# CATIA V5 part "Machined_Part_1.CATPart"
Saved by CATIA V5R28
Part number: Machined_Part
Bounding box of the stored display mesh (mm): x 0 to 279.4, y 0 to 152.586, z 0 to 50.8
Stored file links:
  C:\Users\rsz0866\Documents\007_CATIA_STEP-Files_and_Test_Models\0001_Machined_Parts_Models\Machined_Part_1.CATPart
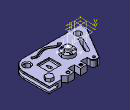
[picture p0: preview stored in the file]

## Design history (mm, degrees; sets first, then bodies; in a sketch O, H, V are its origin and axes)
AxisSystem1: origin (127, 76.2, 50.8), X (1, 0, 0), Y (0, 1, 0), Z (0, 0, 1)
Set1
  Sketch1 on xy-plane, origin (0, 0, 0), H (1, 0, 0), V (0, 1, 0)
    line L1 (0, 0) -> (279.4, 0)
    line L2 (279.4, 0) -> (279.4, 152.5862)
    line L3 (279.4, 152.5862) -> (228.6, 152.5862)
    line L4 (228.6, 152.5862) -> (216.7855, 136.1858)
    line L5 (216.7855, 136.1858) -> (202.7136, 152.5862)
    point P5 (202.7136, 152.5862)
    line L6 (177.3136, 152.5862) -> (177.3136, 127.1862)
    point P6 (177.3136, 152.5862)
    line L7 (202.7136, 152.5862) -> (177.3136, 152.5862)
    line L8 (177.3136, 127.1862) -> (151.9136, 127.1862)
    line L9 (151.9136, 127.1862) -> (151.9136, 152.5862)
    point P9 (151.9136, 152.5862)
    line L10 (151.9136, 152.5862) -> (126.5136, 152.5862)
    line L11 (126.5136, 152.5862) -> (126.5136, 127.1862)
    point P11 (126.5136, 127.1862)
    line L12 (101.1136, 127.1862) -> (101.1136, 152.5862)
    point P12 (101.1136, 127.1862)
    point P13 (101.1136, 152.5862)
    line L13 (101.1136, 152.5862) -> (75.7136, 152.5862)
    line L14 (75.7136, 152.5862) -> (0, 25.4)
    point P15 (0, 25.4)
    line L15 (0, 25.4) -> (0, 0)
    line L16 (101.1136, 127.1862) -> (126.5136, 127.1862)
    length L1 = 279.4
    length L3 = 50.8
    length L7 = 25.4
    length L8 = 25.4
    length L16 = 25.4
    length L10 = 25.4
    length L13 = 25.4
    length L15 = 25.4
    length L6 = 25.4
    horizontal: L1 H, L3 H, L7 H, L8 H, L10 H, L13 H, L16 H
    vertical: L2 V, L6 V, L9 V, L11 V, L12 V, L15 V
    coincidence: P5 L3, P6 L3, P9 L3, P11 L8, P12 L8, P13 L3, P15 V
Body1 (main body)
  Pad1: profile Sketch1, direction (0, 0, 1), length 25.4
  Fillet1: radius 50.8, on edge [face of Pad1 from Sketch1.L2 | face of Pad1 from Sketch1.L1]
  Sketch2 on face of Pad1 from Sketch1.L3, origin (0, 152.5862, 0), H (-1, 0, 0), V (0, 0, 1)
    line L1 (-281.8143, 19.05) -> (-243.7143, 19.05)
    line L2 (-243.7143, 19.05) -> (-243.7143, 6.35)
    line L3 (-243.7143, 6.35) -> (-281.8143, 6.35)
    line L4 (-281.8143, 6.35) -> (-281.8143, 19.05)
    reference projected line E1 (-279.4, 25.4) -> (-228.6, 25.4) from edge [face of Pad1 from Sketch1.L3 | end face of Pad1]
    reference projected line E2 (-279.4, 0) -> (-228.6, 0) from edge [start face of Pad1 | face of Pad1 from Sketch1.L3]
    distance L1 E1 = 6.35
    distance L3 E2 = 6.35
    length L1 = 38.1
    horizontal: L1 H, L3 H
    vertical: L2 V, L4 V
  Pocket1: profile Sketch2, direction (0, -1, 0), length 152.4
  Sketch3 on end face of Pad1, origin (0, 0, 25.4), H (1, 0, 0), V (0, 1, 0)
    circle A1 centre (247.65, 31.75) radius 12.7
    point P1 (247.65, 31.75)
    reference projected line E1 (0, 0) -> (279.4, 0) from edge [face of Pad1 from Sketch1.L1 | end face of Pad1]
    reference projected line E2 (279.4, 0) -> (279.4, 152.5862) from edge [face of Pad1 from Sketch1.L2 | end face of Pad1]
    radius A1 = 12.7
    distance E1 P1 = 31.75
    distance E2 P1 = 31.75
  Pocket2: profile Sketch3, direction (0, 0, -1), through (limit type 3)
  Fillet2: radius 3.175, on edge [end face of Pad1 | face of Pocket2 from Sketch3.A1]
  Fillet3: radius 3.175, on edge [face of Pocket2 from Sketch3.A1 | start face of Pad1]
  Sketch4 on end face of Pad1, origin (35.564, 25.318, 25.4), H (1, 0, 0), V (0, 1, 0)
    point P1 (0, 0)
  Hole1: placed by Sketch4, at (35.564, 25.318, 25.4) direction (0, 0, -1), diameter 12.7, through (limit type 3), type TaperedType, Diameter 12.7, DiameterThread 11, Pas 1, Sketch Sketch4, ThreadDepth 10, Angle 30
  Fillet4: radius 12.7, on edge [face of Pad1 from Sketch1.L13 | face of Pad1 from Sketch1.L12]
  Fillet5: radius 12.7, on edge [face of Pad1 from Sketch1.L14 | face of Pad1 from Sketch1.L13]
  Sketch5 on end face of Pad1, origin (0, 0, 25.4), H (1, 0, 0), V (0, 1, 0)
    spline S1 through (101.9757, 24.9195) (126.5342, 31.4551) (156.095, 16.9999) (186.1894, 24.9195) (218.6664, 20.7127)
  Pocket3: profile Sketch5, direction (0, 0, -1), length 7.62, opposite side length 12.7, thin wall 10.16
  Fillet6: radius 1.27, on end face of Pocket3
  Sketch6 on end face of Pad1, origin (138.456, 140.6438, 25.4), H (1, 0, 0), V (0, 1, 0)
    point P1 (0, 0)
  Hole2: placed by Sketch6, at (138.456, 140.6438, 25.4) direction (0, 0, -1), diameter 6.9088, through (limit type 3), counterbore diameter 12.7, counterbore depth 3.175, threaded ".3125-24 UNF-1B", thread diameter 7.9375, thread depth 10, pitch 1.0592
  Chamfer1: length 1, angle 45, on edge [face of Pad1 from Sketch1.L14 | end face of Pad1]
  Chamfer2: length 1, angle 45, on edge [face of Pad1 from Sketch1.L15 | end face of Pad1]
  Chamfer3: length 1, angle 45, on edge [face of Pad1 from Sketch1.L1 | end face of Pad1]; edge [end face of Pad1 | face of Fillet1]; edge [face of Pad1 from Sketch1.L2 | end face of Pad1]
  Chamfer4: length 3.175, angle 45, on edge [face of Pad1 from Sketch1.L5 | face of Pad1 from Sketch1.L4]
  Sketch7 on end face of Pad1, origin (0, 0, 25.4), H (1, 0, 0), V (0, 1, 0)
    construction line L1 (50.2082, 50.7866) -> (75.5763, 101.7715)
    line L2 (43.6422, 54.0536) -> (69.0103, 105.0385)
    line L3 (82.1424, 98.5045) -> (56.7742, 47.5196)
    arc A1 centre (75.5763, 101.7715) radius 7.3339 from (69.0103, 105.0385) to (82.1424, 98.5045) cw
    arc A2 centre (50.2082, 50.7866) radius 7.3339 from (56.7742, 47.5196) to (43.6422, 54.0536) cw
    distance L1 L2 = 7.3339
    tangency: A1 L2, A2 L2, A1 L3, A2 L3
  Pocket4: profile Sketch7, direction (0, 0, -1), through (limit type 3)
  Sketch8 on end face of Pad1, origin (84.614, 137.1599, 25.4), H (1, 0, 0), V (0, 1, 0)
    point P1 (0, 1.7263)
    reference projected line E1 (3.7996, 14.4263) -> (-1.6807, 14.4263) from edge [face of Chamfer1 | end face of Pad1]
    distance P1 E1 = 12.7
  Hole3: placed by Sketch8, at (84.614, 138.8862, 25.4) direction (0, 0, -1), diameter 6.9088, through (limit type 3), countersink depth 3.175, countersink angle 45
  Sketch9 on end face of Pad1, origin (190.6626, 140.5352, 25.4), H (1, 0, 0), V (0, 1, 0)
    point P1 (0, 0)
  Hole4: placed by Sketch9, at (190.6626, 140.5352, 25.4) direction (0, 0, -1), diameter 6.9088, depth 19.05, V-bottom angle 120, type CounterDrilledType, Diameter 6.9088, DiameterThread 7.5997, Pas 1, Sketch Sketch9, ThreadDepth 10, Angle 45, Depth 3.175, Diameter 12.7, CounterSunkDiameter 12
  Sketch10 on end face of Pad1, origin (0, 0, 25.4), H (1, 0, 0), V (0, 1, 0)
    circle A1 centre (127, 76.2) radius 25.4
    radius A1 = 25.4
  Pad2: profile Sketch10, direction (0, 0, 1), length 12.7
  Sketch11 on end face of Pad2, origin (0, 0, 38.1), H (1, 0, 0), V (0, 1, 0)
    circle A1 centre (127, 76.2) radius 12.7
    radius A1 = 12.7
  Pad3: profile Sketch11, direction (0, 0, 1), length 12.7
  Sketch12 on end face of Pad2, origin (146.05, 76.2, 38.1), H (1, 0, 0), V (0, 1, 0)
    point P1 (0, 0)
    reference projected point E1 (0, 0) from Sketch16.P1
    coincidence: E1 P1
  Hole5: placed by Sketch12, at (146.05, 76.2, 38.1) direction (0, 0, -1), diameter 6.35, through (limit type 3), countersink depth 3.175, countersink angle 45
  CircPattern1: of Hole5, instances 5, angular step 72, axis from edge [ZX plane of AxisSystem1 | YZ plane of AxisSystem1]
  Sketch13 on end face of Pad1, origin (0, 0, 25.4), H (1, 0, 0), V (0, 1, 0)
    point P2 (254.1655, 115.3359)
    construction circle A1 centre (254.1655, 128.0359) radius 14.6647
    construction circle A2 centre (254.1655, 128.0359) radius 12.7
    point P3 (246.8331, 115.3359)
    point P4 (261.4978, 115.3359)
    point P5 (268.8302, 128.0359)
    point P6 (261.4978, 140.7359)
    point P7 (246.8331, 140.7359)
    point P8 (239.5008, 128.0359)
    line L1 (246.8331, 115.3359) -> (261.4978, 115.3359)
    line L2 (261.4978, 115.3359) -> (268.8302, 128.0359)
    line L3 (268.8302, 128.0359) -> (261.4978, 140.7359)
    line L4 (261.4978, 140.7359) -> (246.8331, 140.7359)
    line L5 (246.8331, 140.7359) -> (239.5008, 128.0359)
    line L6 (239.5008, 128.0359) -> (246.8331, 115.3359)
    construction line L7 (254.1655, 128.0359) -> (254.1655, 115.3359)
    distance L1 L4 = 25.4
    coincidence: A1 P3, A1 P4, A1 P5, A1 P6, A1 P7, A1 P8
    tangency: A2 L1, A2 L2, A2 L3, A2 L4, A2 L5, A2 L6
    midpoint: P2 L1
    vertical: L7 V
  Pad4: profile Sketch13, direction (0, 0, 1), length 12.7
  Sketch14 on end face of Pad1, origin (0, 0, 25.4), H (1, 0, 0), V (0, 1, 0)
    line L1 (177.8, 101.6) -> (228.6, 101.6)
    line L2 (228.6, 101.6) -> (228.6, 50.8)
    line L3 (228.6, 50.8) -> (177.8, 50.8)
    line L4 (177.8, 50.8) -> (177.8, 101.6)
    horizontal: L1 H, L3 H
    vertical: L2 V, L4 V
  Pocket5: profile Sketch14, direction (0, 0, -1), length 7.62
  Fillet7: radius 3.175, on edge [face of Pocket5 from Sketch14.L1 | end face of Pocket5]; edge [face of Pocket5 from Sketch14.L2 | end face of Pocket5]; edge [face of Pocket5 from Sketch14.L4 | end face of Pocket5]; edge [face of Pocket5 from Sketch14.L3 | end face of Pocket5]
  Sketch15 on end face of Pocket5, origin (0, 0, 17.78), H (1, 0, 0), V (0, 1, 0)
    construction line L1 (203.2, 81.28) -> (203.2, 68.58)
    line L2 (199.6079, 68.58) -> (199.6079, 76.8806)
    line L3 (206.7921, 76.8806) -> (206.7921, 68.58)
    arc A1 centre (203.2, 81.28) radius 5.6796 from (199.6079, 76.8806) to (206.7921, 76.8806) cw
    arc A2 centre (203.2, 68.58) radius 3.5921 from (206.7921, 68.58) to (199.6079, 68.58) cw
    radius A1 = 5.6796
    radius A2 = 3.5921
    vertical: L1 V
    tangency: A2 L2, A2 L3
    parallelism: L2 L3, L2 L1
  Pocket6: profile Sketch15, direction (0, 0, -1), through (limit type 3)
  Sketch16 on end face of Pad2, origin (0, 0, 38.1), H (1, 0, 0), V (0, 1, 0)
    point P1 (146.05, 76.2)
    reference projected point E1 (127, 76.2) from Sketch17
    distance P1 E1 = 19.05
  Sketch17 on end face of Pad3, origin (0, 0, 50.8), H (1, 0, 0), V (0, 1, 0)
    point P1 (127, 76.2)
